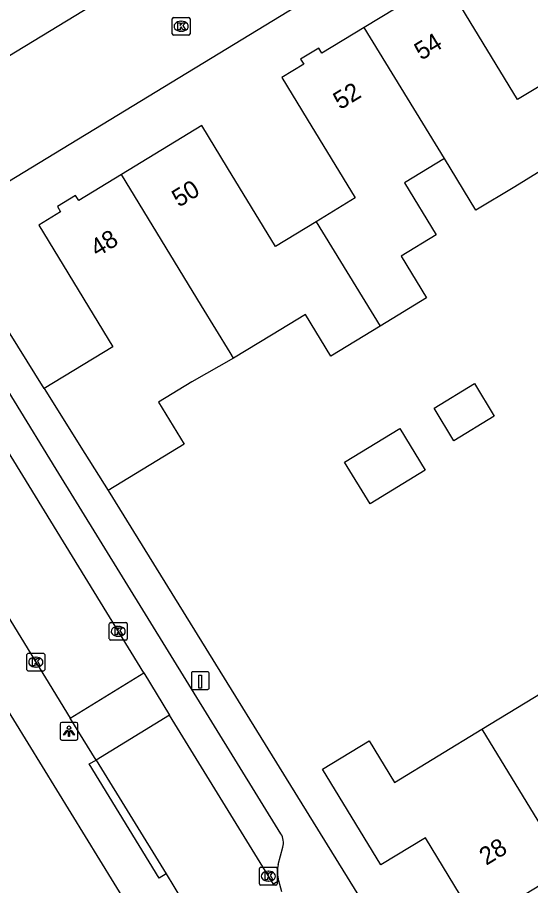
# Model space of a CAD drawing. Extents: x 157767 to 159171, y 387842 to 389425.
# Drawn here: x 158219.55 to 158248.51, y 388431.41 to 388480.38 of the extents above; entities that cross this region are included whole.
import ezdxf

# ---------------------------------------------------------------- set-up
doc = ezdxf.new("R2010")
doc.units = 0
for name, color, linetype in [('IMGEO_Kolk', 7, 'Continuous'), ('IMGEO_Laadpaal', 7, 'Continuous'), ('IMGEO_Lichtpunt', 7, 'Continuous'), ('IMGEO_Pand', 7, 'Continuous'), ('IMGEO_Pand_nummerreeks', 7, 'Continuous'), ('IMGEO_Rijbaan_lokaal_open', 7, 'Continuous'), ('IMGEO_Voetpad_open', 7, 'Continuous')]:
    doc.layers.add(name, color=color, linetype=linetype)

msp = doc.modelspace()

# ---------------------------------------------------------------- linework, layer by layer
at = {"layer": 'IMGEO_Kolk'}
for p, q in [((158228.365, 388480.378), (158229.217, 388480.378)), ((158228.29, 388479.452), (158228.29, 388480.304)), ((158228.778, 388480.158), (158228.803, 388480.158)), ((158229.291, 388480.304), (158229.291, 388479.452)), ((158228.801, 388479.598), (158228.776, 388479.598)), ((158229.217, 388479.378), (158228.365, 388479.378)), ((158224.737, 388445.321), (158224.737, 388446.173)), ((158224.812, 388446.247), (158225.664, 388446.247)), ((158225.738, 388446.173), (158225.738, 388445.321)), ((158225.225, 388446.027), (158225.25, 388446.027)), ((158225.664, 388445.247), (158224.812, 388445.247)), ((158225.248, 388445.467), (158225.223, 388445.467)), ((158220.09, 388443.585), (158220.09, 388444.437)), ((158220.165, 388444.511), (158221.017, 388444.511)), ((158220.578, 388444.291), (158220.603, 388444.291)), ((158221.091, 388444.437), (158221.091, 388443.585)), ((158220.601, 388443.731), (158220.576, 388443.731)), ((158221.017, 388443.511), (158220.165, 388443.511)), ((158233.285, 388432.438), (158234.137, 388432.438)), ((158233.21, 388431.512), (158233.21, 388432.364)), ((158233.698, 388432.218), (158233.723, 388432.218)), ((158234.211, 388432.364), (158234.211, 388431.512)), ((158234.137, 388431.438), (158233.285, 388431.438)), ((158233.721, 388431.658), (158233.696, 388431.658))]:
    msp.add_line(p, q, dxfattribs=at)
for points in [[(158228.365, 388480.378), (158229.217, 388480.378)], [(158228.29, 388479.452), (158228.29, 388480.304)], [(158228.611, 388480.078), (158228.734, 388480.078), (158228.734, 388479.927), (158228.864, 388480.078), (158229.028, 388480.078), (158228.882, 388479.927), (158229.035, 388479.678), (158228.883, 388479.678), (158228.798, 388479.842), (158228.734, 388479.775), (158228.734, 388479.678), (158228.611, 388479.678), (158228.611, 388480.078)], [(158229.291, 388480.304), (158229.291, 388479.452)], [(158229.217, 388479.378), (158228.365, 388479.378)], [(158224.737, 388445.321), (158224.737, 388446.173)], [(158224.812, 388446.247), (158225.664, 388446.247)], [(158225.738, 388446.173), (158225.738, 388445.321)], [(158225.058, 388445.947), (158225.181, 388445.947), (158225.181, 388445.796), (158225.311, 388445.947), (158225.475, 388445.947), (158225.329, 388445.796), (158225.482, 388445.547), (158225.33, 388445.547), (158225.245, 388445.711), (158225.181, 388445.644), (158225.181, 388445.547), (158225.058, 388445.547), (158225.058, 388445.947)], [(158225.664, 388445.247), (158224.812, 388445.247)], [(158220.09, 388443.585), (158220.09, 388444.437)], [(158220.165, 388444.511), (158221.017, 388444.511)], [(158220.411, 388444.211), (158220.534, 388444.211), (158220.534, 388444.06), (158220.664, 388444.211), (158220.828, 388444.211), (158220.682, 388444.06), (158220.835, 388443.811), (158220.683, 388443.811), (158220.598, 388443.975), (158220.534, 388443.908), (158220.534, 388443.811), (158220.411, 388443.811), (158220.411, 388444.211)], [(158221.091, 388444.437), (158221.091, 388443.585)], [(158221.017, 388443.511), (158220.165, 388443.511)], [(158233.285, 388432.438), (158234.137, 388432.438)], [(158233.21, 388431.512), (158233.21, 388432.364)], [(158233.531, 388432.138), (158233.654, 388432.138), (158233.654, 388431.987), (158233.784, 388432.138), (158233.948, 388432.138), (158233.802, 388431.987), (158233.955, 388431.738), (158233.803, 388431.738), (158233.718, 388431.902), (158233.654, 388431.835), (158233.654, 388431.738), (158233.531, 388431.738), (158233.531, 388432.138)], [(158234.211, 388432.364), (158234.211, 388431.512)], [(158234.137, 388431.438), (158233.285, 388431.438)]]:
    msp.add_lwpolyline(points, dxfattribs=at)
for centre, start, end in [((158228.367, 388480.302), 91.552, 178.448), ((158228.367, 388480.302), 91.552, 178.448), ((158229.215, 388480.302), 1.552, 88.448), ((158229.215, 388480.302), 1.552, 88.448), ((158228.367, 388479.454), 181.552, 268.448), ((158228.367, 388479.454), 181.552, 268.448), ((158229.215, 388479.454), 271.552, 358.448), ((158229.215, 388479.454), 271.552, 358.448), ((158224.814, 388446.171), 91.552, 178.448), ((158224.814, 388446.171), 91.552, 178.448), ((158225.662, 388446.171), 1.552, 88.448), ((158225.662, 388446.171), 1.552, 88.448), ((158224.814, 388445.323), 181.552, 268.448), ((158224.814, 388445.323), 181.552, 268.448), ((158225.662, 388445.323), 271.552, 358.448), ((158225.662, 388445.323), 271.552, 358.448), ((158220.167, 388444.435), 91.552, 178.448), ((158220.167, 388444.435), 91.552, 178.448), ((158221.015, 388444.435), 1.552, 88.448), ((158221.015, 388444.435), 1.552, 88.448), ((158220.167, 388443.587), 181.552, 268.448), ((158220.167, 388443.587), 181.552, 268.448), ((158221.015, 388443.587), 271.552, 358.448), ((158221.015, 388443.587), 271.552, 358.448), ((158233.287, 388432.362), 91.552, 178.448), ((158233.287, 388432.362), 91.552, 178.448), ((158234.135, 388432.362), 1.552, 88.448), ((158234.135, 388432.362), 1.552, 88.448), ((158233.287, 388431.514), 181.552, 268.448), ((158233.287, 388431.514), 181.552, 268.448), ((158234.135, 388431.514), 271.552, 358.448), ((158234.135, 388431.514), 271.552, 358.448)]:
    msp.add_arc(centre, 0.0765, start, end, dxfattribs=at)
for centre, major_axis, ratio, start_param, end_param in [((158228.777, 388479.878), (-0.387, 0.002), 0.722429, 4.712389, 7.853982), ((158228.802, 388479.878), (-0.39, 0.002), 0.717154, 1.570796, 4.712389), ((158225.224, 388445.747), (-0.387, 0.002), 0.722429, 4.712389, 7.853982), ((158225.249, 388445.747), (-0.39, 0.002), 0.717154, 1.570796, 4.712389), ((158220.577, 388444.011), (-0.387, 0.002), 0.722429, 4.712389, 7.853982), ((158220.602, 388444.011), (-0.39, 0.002), 0.717154, 1.570796, 4.712389), ((158233.697, 388431.938), (-0.387, 0.002), 0.722429, 4.712389, 7.853982), ((158233.722, 388431.938), (-0.39, 0.002), 0.717154, 1.570796, 4.712389)]:
    msp.add_ellipse(centre, major_axis=major_axis, ratio=ratio, start_param=start_param, end_param=end_param, dxfattribs=at)
at = {"layer": 'IMGEO_Laadpaal'}
for p, q in [((158229.366, 388443.387), (158229.366, 388442.546)), ((158229.366, 388443.387), (158229.366, 388442.546)), ((158230.282, 388443.471), (158229.441, 388443.471)), ((158230.282, 388443.471), (158229.441, 388443.471)), ((158230.366, 388442.555), (158230.366, 388443.396)), ((158230.366, 388442.555), (158230.366, 388443.396)), ((158229.45, 388442.471), (158230.291, 388442.471)), ((158229.45, 388442.471), (158230.291, 388442.471))]:
    msp.add_line(p, q, dxfattribs=at)
msp.add_lwpolyline([(158229.781, 388443.284), (158229.941, 388443.284), (158229.941, 388442.551), (158229.781, 388442.551), (158229.781, 388443.284)], dxfattribs=at)
for centre, start, end in [((158229.444, 388443.393), 92.4484, 184.2845), ((158229.444, 388443.393), 92.4484, 184.2845), ((158230.288, 388443.393), 2.4484, 94.2845), ((158230.288, 388443.393), 2.4484, 94.2845), ((158229.444, 388442.549), 182.4484, 274.2845), ((158229.444, 388442.549), 182.4484, 274.2845), ((158230.288, 388442.549), 272.4484, 4.2845), ((158230.288, 388442.549), 272.4484, 4.2845)]:
    msp.add_arc(centre, 0.0779, start, end, dxfattribs=at)
at = {"layer": 'IMGEO_Lichtpunt'}
for p, q in [((158221.964, 388440.517), (158221.964, 388439.71)), ((158221.964, 388440.517), (158221.964, 388439.71)), ((158222.866, 388440.612), (158222.058, 388440.612)), ((158222.866, 388440.612), (158222.058, 388440.612)), ((158222.96, 388439.71), (158222.96, 388440.517)), ((158222.96, 388439.71), (158222.96, 388440.517)), ((158222.058, 388439.616), (158222.866, 388439.616)), ((158222.058, 388439.616), (158222.866, 388439.616))]:
    msp.add_line(p, q, dxfattribs=at)
for points in [[(158222.338, 388440.181), (158222.377, 388440.153), (158222.189, 388439.891), (158222.151, 388439.918), (158222.338, 388440.181)], [(158222.44, 388440.133), (158222.487, 388440.133), (158222.487, 388439.811), (158222.44, 388439.811), (158222.44, 388440.133)], [(158222.55, 388440.153), (158222.588, 388440.18), (158222.775, 388439.918), (158222.736, 388439.89), (158222.55, 388440.153)]]:
    msp.add_lwpolyline(points, dxfattribs=at)
msp.add_circle((158222.463, 388440.315), 0.0994, dxfattribs=at)
for centre, start, end in [((158222.058, 388440.517), 90, 180), ((158222.058, 388440.517), 90, 180), ((158222.866, 388440.517), 0, 90), ((158222.866, 388440.517), 0, 90), ((158222.058, 388439.71), 180, 270), ((158222.058, 388439.71), 180, 270), ((158222.866, 388439.71), 270, 0), ((158222.866, 388439.71), 270, 360)]:
    msp.add_arc(centre, 0.0946, start, end, dxfattribs=at)
at = {"layer": 'IMGEO_Pand'}
for points in [[(158250.071, 388477.146), (158247.771, 388475.744), (158243.621, 388482.556), (158239.11, 388479.809)], [(158239.11, 388479.809), (158236.729, 388478.359), (158236.552, 388478.649), (158235.527, 388478.024), (158235.703, 388477.733), (158234.473, 388476.983), (158235.905, 388474.633), (158238.61, 388470.192), (158236.405, 388468.849)], [(158243.641, 388472.416), (158239.11, 388479.809)], [(158236.405, 388468.849), (158234.11, 388467.451), (158231.405, 388471.892), (158229.955, 388474.272), (158225.432, 388471.518)], [(158243.641, 388472.416), (158241.392, 388471.047), (158243.175, 388468.12), (158241.199, 388466.916), (158242.635, 388464.559), (158240.008, 388462.958)], [(158253.671, 388471.339), (158250.953, 388469.683), (158249.539, 388472.005), (158247.608, 388470.829), (158245.419, 388469.496), (158243.641, 388472.416)], [(158225.432, 388471.518), (158223.01, 388470.043), (158222.833, 388470.333), (158221.808, 388469.708), (158221.984, 388469.417), (158220.754, 388468.667), (158224.935, 388461.804), (158221.068, 388459.446)], [(158231.745, 388461.15), (158231.547, 388461.474), (158229.941, 388464.112), (158225.432, 388471.518)], [(158236.405, 388468.849), (158240.008, 388462.958)], [(158240.008, 388462.958), (158237.241, 388461.273), (158235.808, 388463.626), (158233.89, 388462.457), (158231.745, 388461.15)], [(158231.745, 388461.15), (158229.398, 388459.826), (158227.504, 388458.673), (158228.951, 388456.298), (158224.669, 388453.69)], [(158221.068, 388459.446), (158223.359, 388455.784), (158224.669, 388453.69)], [(158246.452, 388457.885), (158244.176, 388456.499), (158243.054, 388458.341), (158245.33, 388459.727), (158246.452, 388457.885)], [(158242.561, 388454.845), (158239.444, 388452.948), (158238.013, 388455.297), (158241.13, 388457.195), (158242.561, 388454.845)], [(158245.761, 388440.23), (158250.638, 388443.198), (158249.213, 388445.539), (158251.798, 388447.112)], [(158250.56, 388432.347), (158245.513, 388429.275), (158242.573, 388434.106), (158240.057, 388432.575), (158236.769, 388437.979), (158239.402, 388439.581), (158240.832, 388437.231), (158245.761, 388440.23)], [(158245.761, 388440.23), (158250.56, 388432.347)]]:
    msp.add_lwpolyline(points, dxfattribs=at)
at = {"layer": 'IMGEO_Rijbaan_lokaal_open'}
for points in [[(158248.901, 388489.285), (158216.837, 388469.76), (158216.112, 388467.591)], [(158227.985, 388483.627), (158217.602, 388477.304)], [(158226.677, 388443.402), (158214.083, 388463.926)], [(158218.343, 388447.668), (158222.532, 388440.859)], [(158222.532, 388440.859), (158226.677, 388443.402)], [(158226.677, 388443.402), (158228.136, 388441.024)], [(158223.994, 388438.483), (158222.532, 388440.859)], [(158228.136, 388441.024), (158223.994, 388438.483)], [(158234.3, 388431.678), (158233.991, 388431.481), (158228.136, 388441.024)], [(158223.994, 388438.483), (158227.938, 388432.071)], [(158227.938, 388432.071), (158228.817, 388430.643)], [(158234.466, 388431.055), (158234.3, 388431.678)]]:
    msp.add_lwpolyline(points, dxfattribs=at)
at = {"layer": 'IMGEO_Voetpad_open'}
for points in [[(158221.068, 388459.446), (158216.064, 388467.448), (158216.112, 388467.591)], [(158234.417, 388434.33), (158221.747, 388454.893), (158217.021, 388462.563)], [(158206.731, 388361.142), (158207.656, 388363.849), (158211.167, 388374.122), (158210.098, 388376.863), (158227.437, 388427.591), (158206.398, 388461.811)], [(158224.669, 388453.69), (158240.217, 388428.536)], [(158227.938, 388432.071), (158227.555, 388431.831), (158223.593, 388438.27), (158223.994, 388438.483)], [(158234.268, 388432.589), (158234.529, 388433.572)], [(158234.3, 388431.678), (158234.268, 388431.798)]]:
    msp.add_lwpolyline(points, dxfattribs=at)
for centre, radius, start, end in [((158233.592, 388433.821), 0.969, 345.1264, 31.6837), ((158235.776, 388432.193), 1.559, 165.3044, 194.6956)]:
    msp.add_arc(centre, radius, start, end, dxfattribs=at)

# ---------------------------------------------------------------- texts
at = {"layer": 'IMGEO_Pand_nummerreeks'}
for s, rotation, p in [('54', 31.3499, (158242.335, 388477.932)), ('52', 31.3499, (158237.758, 388475.144)), ('50', 31.3465, (158228.658, 388469.641)), ('48', 31.3465, (158224.058, 388466.839)), ('28', 31.324, (158245.999, 388432.52))]:
    msp.add_text(s, height=1, rotation=rotation, dxfattribs=at).set_placement(p)

doc.saveas('drawing.dxf')
